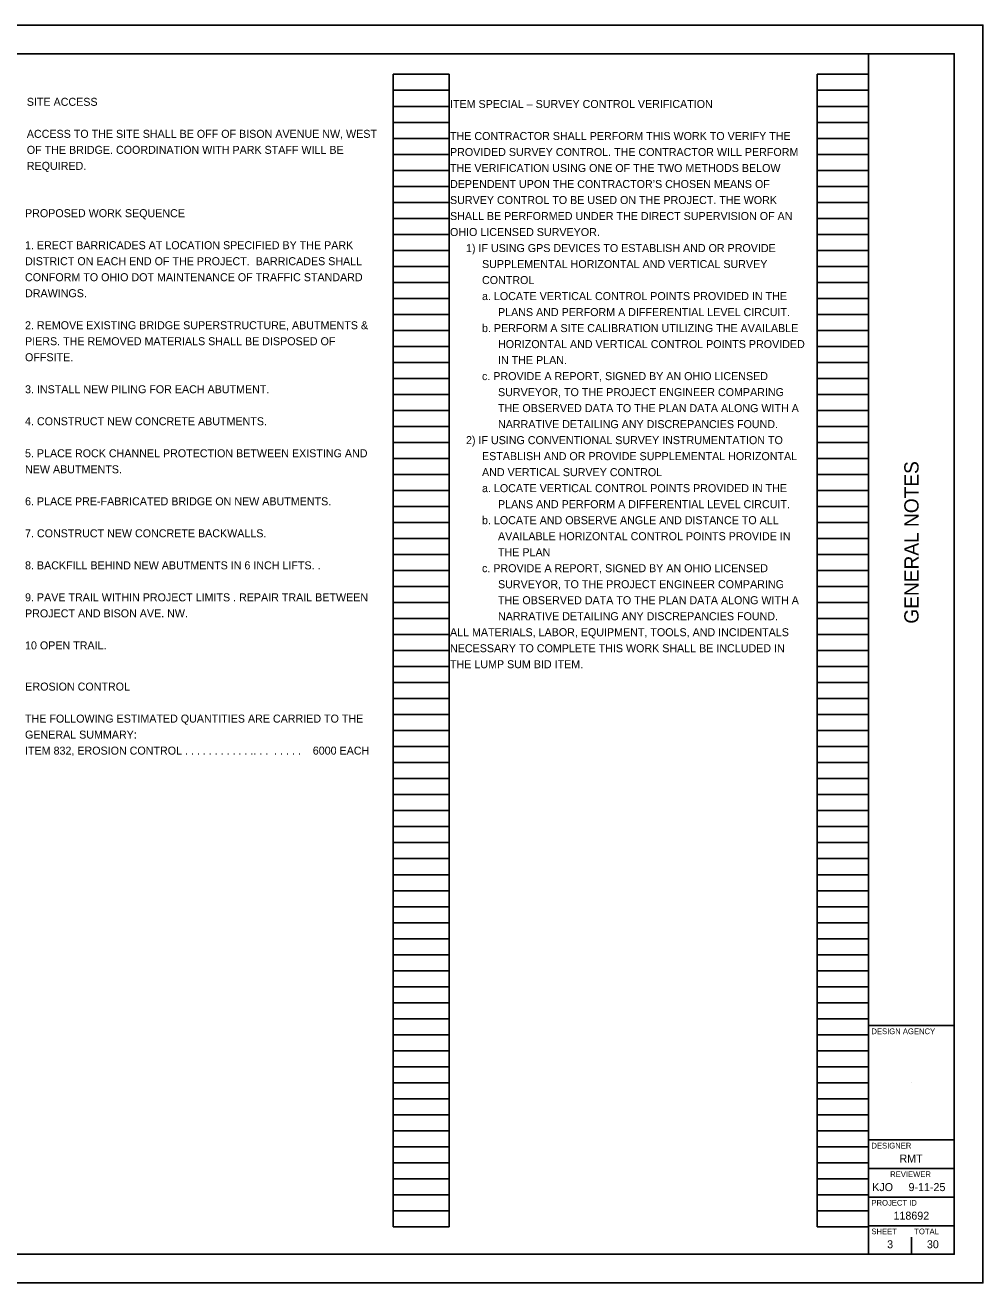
# Model space of a CAD drawing. Extents: x 4.7 to 38.7, y 13.7 to 35.7.
# Drawn here: x 21.95 to 38.7, y 13.71 to 35.71 of the extents above; entities that cross this region are included whole.
import ezdxf

# ---------------------------------------------------------------- set-up
doc = ezdxf.new("R2010")
doc.units = 0
for name, color, linetype in [('SH_Border', 7, 'Continuous'), ('SH_Cut_Line', 7, 'Continuous'), ('SH_Data', 7, 'Continuous'), ('SH_Text', 7, 'Continuous')]:
    doc.layers.add(name, color=color, linetype=linetype)

msp = doc.modelspace()

# ---------------------------------------------------------------- linework, layer by layer
at = {"layer": 'SH_Border'}
for p, q in [((36.705, 14.212), (36.705, 35.212)), ((36.705, 18.212), (38.205, 18.212)), ((36.705, 16.212), (38.205, 16.212)), ((36.705, 15.712), (38.205, 15.712)), ((36.705, 15.212), (38.205, 15.212)), ((36.705, 14.712), (38.205, 14.712))]:
    msp.add_line(p, q, dxfattribs=at)
msp.add_lwpolyline([(6.205, 35.212), (38.205, 35.212), (38.205, 14.212), (6.205, 14.212)], close=True, dxfattribs=at)
at = {"layer": 'SH_Cut_Line'}
msp.add_lwpolyline([(4.705, 13.712), (38.705, 13.712), (38.705, 35.712), (4.705, 35.712)], close=True, dxfattribs=at)
at = {"layer": 'SH_Data'}
for p, q in [((28.385, 14.692), (28.385, 34.852)), ((28.385, 34.852), (29.365, 34.852)), ((29.365, 14.692), (29.365, 34.852)), ((35.805, 14.692), (35.805, 34.852)), ((35.805, 34.852), (36.705, 34.852)), ((36.705, 14.692), (36.705, 34.852)), ((28.385, 34.572), (29.365, 34.572)), ((35.805, 34.572), (36.705, 34.572)), ((28.385, 34.292), (29.365, 34.292)), ((35.805, 34.292), (36.705, 34.292)), ((28.385, 34.012), (29.365, 34.012)), ((35.805, 34.012), (36.705, 34.012)), ((28.385, 33.732), (29.365, 33.732)), ((35.805, 33.732), (36.705, 33.732)), ((28.385, 33.452), (29.365, 33.452)), ((35.805, 33.452), (36.705, 33.452)), ((28.385, 33.172), (29.365, 33.172)), ((35.805, 33.172), (36.705, 33.172)), ((28.385, 32.892), (29.365, 32.892)), ((35.805, 32.892), (36.705, 32.892)), ((28.385, 32.612), (29.365, 32.612)), ((35.805, 32.612), (36.705, 32.612)), ((28.385, 32.332), (29.365, 32.332)), ((35.805, 32.332), (36.705, 32.332)), ((28.385, 32.052), (29.365, 32.052)), ((35.805, 32.052), (36.705, 32.052)), ((28.385, 31.772), (29.365, 31.772)), ((35.805, 31.772), (36.705, 31.772)), ((28.385, 31.492), (29.365, 31.492)), ((35.805, 31.492), (36.705, 31.492)), ((28.385, 31.212), (29.365, 31.212)), ((35.805, 31.212), (36.705, 31.212)), ((28.385, 30.932), (29.365, 30.932)), ((35.805, 30.932), (36.705, 30.932)), ((28.385, 30.652), (29.365, 30.652)), ((35.805, 30.652), (36.705, 30.652)), ((28.385, 30.372), (29.365, 30.372)), ((35.805, 30.372), (36.705, 30.372)), ((28.385, 30.092), (29.365, 30.092)), ((35.805, 30.092), (36.705, 30.092)), ((28.385, 29.812), (29.365, 29.812)), ((35.805, 29.812), (36.705, 29.812)), ((28.385, 29.532), (29.365, 29.532)), ((35.805, 29.532), (36.705, 29.532)), ((28.385, 29.252), (29.365, 29.252)), ((35.805, 29.252), (36.705, 29.252)), ((28.385, 28.972), (29.365, 28.972)), ((35.805, 28.972), (36.705, 28.972)), ((28.385, 28.692), (29.365, 28.692)), ((35.805, 28.692), (36.705, 28.692)), ((28.385, 28.412), (29.365, 28.412)), ((35.805, 28.412), (36.705, 28.412)), ((28.385, 28.132), (29.365, 28.132)), ((35.805, 28.132), (36.705, 28.132)), ((28.385, 27.852), (29.365, 27.852)), ((35.805, 27.852), (36.705, 27.852)), ((28.385, 27.572), (29.365, 27.572)), ((35.805, 27.572), (36.705, 27.572)), ((28.385, 27.292), (29.365, 27.292)), ((35.805, 27.292), (36.705, 27.292)), ((28.385, 27.012), (29.365, 27.012)), ((35.805, 27.012), (36.705, 27.012)), ((28.385, 26.732), (29.365, 26.732)), ((35.805, 26.732), (36.705, 26.732)), ((28.385, 26.452), (29.365, 26.452)), ((35.805, 26.452), (36.705, 26.452)), ((28.385, 26.172), (29.365, 26.172)), ((35.805, 26.172), (36.705, 26.172)), ((28.385, 25.892), (29.365, 25.892)), ((35.805, 25.892), (36.705, 25.892)), ((28.385, 25.612), (29.365, 25.612)), ((35.805, 25.612), (36.705, 25.612)), ((28.385, 25.332), (29.365, 25.332)), ((35.805, 25.332), (36.705, 25.332)), ((28.385, 25.052), (29.365, 25.052)), ((35.805, 25.052), (36.705, 25.052)), ((28.385, 24.772), (29.365, 24.772)), ((35.805, 24.772), (36.705, 24.772)), ((28.385, 24.492), (29.365, 24.492)), ((35.805, 24.492), (36.705, 24.492)), ((28.385, 24.212), (29.365, 24.212)), ((35.805, 24.212), (36.705, 24.212)), ((28.385, 23.932), (29.365, 23.932)), ((35.805, 23.932), (36.705, 23.932)), ((28.385, 23.652), (29.365, 23.652)), ((35.805, 23.652), (36.705, 23.652)), ((28.385, 23.372), (29.365, 23.372)), ((35.805, 23.372), (36.705, 23.372)), ((28.385, 23.092), (29.365, 23.092)), ((35.805, 23.092), (36.705, 23.092)), ((28.385, 22.812), (29.365, 22.812)), ((35.805, 22.812), (36.705, 22.812)), ((28.385, 22.532), (29.365, 22.532)), ((35.805, 22.532), (36.705, 22.532)), ((28.385, 22.252), (29.365, 22.252)), ((35.805, 22.252), (36.705, 22.252)), ((28.385, 21.972), (29.365, 21.972)), ((35.805, 21.972), (36.705, 21.972)), ((28.385, 21.692), (29.365, 21.692)), ((35.805, 21.692), (36.705, 21.692)), ((28.385, 21.412), (29.365, 21.412)), ((35.805, 21.412), (36.705, 21.412)), ((28.385, 21.132), (29.365, 21.132)), ((35.805, 21.132), (36.705, 21.132)), ((28.385, 20.852), (29.365, 20.852)), ((35.805, 20.852), (36.705, 20.852)), ((28.385, 20.572), (29.365, 20.572)), ((35.805, 20.572), (36.705, 20.572)), ((28.385, 20.292), (29.365, 20.292)), ((35.805, 20.292), (36.705, 20.292)), ((28.385, 20.012), (29.365, 20.012)), ((35.805, 20.012), (36.705, 20.012)), ((28.385, 19.732), (29.365, 19.732)), ((35.805, 19.732), (36.705, 19.732)), ((28.385, 19.452), (29.365, 19.452)), ((35.805, 19.452), (36.705, 19.452)), ((28.385, 19.172), (29.365, 19.172)), ((35.805, 19.172), (36.705, 19.172)), ((28.385, 18.892), (29.365, 18.892)), ((35.805, 18.892), (36.705, 18.892)), ((28.385, 18.612), (29.365, 18.612)), ((35.805, 18.612), (36.705, 18.612)), ((28.385, 18.332), (29.365, 18.332)), ((35.805, 18.332), (36.705, 18.332)), ((28.385, 18.052), (29.365, 18.052)), ((35.805, 18.052), (36.705, 18.052)), ((28.385, 17.772), (29.365, 17.772)), ((35.805, 17.772), (36.705, 17.772)), ((28.385, 17.492), (29.365, 17.492)), ((35.805, 17.492), (36.705, 17.492)), ((28.385, 17.212), (29.365, 17.212)), ((35.805, 17.212), (36.705, 17.212)), ((37.455, 17.212), (37.455, 17.212)), ((28.385, 16.932), (29.365, 16.932)), ((35.805, 16.932), (36.705, 16.932)), ((28.385, 16.652), (29.365, 16.652)), ((35.805, 16.652), (36.705, 16.652)), ((28.385, 16.372), (29.365, 16.372)), ((35.805, 16.372), (36.705, 16.372)), ((28.385, 16.092), (29.365, 16.092)), ((35.805, 16.092), (36.705, 16.092)), ((28.385, 15.812), (29.365, 15.812)), ((35.805, 15.812), (36.705, 15.812)), ((28.385, 15.532), (29.365, 15.532)), ((35.805, 15.532), (36.705, 15.532)), ((28.385, 15.252), (29.365, 15.252)), ((35.805, 15.252), (36.705, 15.252)), ((28.385, 14.972), (29.365, 14.972)), ((35.805, 14.972), (36.705, 14.972)), ((28.385, 14.692), (29.365, 14.692)), ((35.805, 14.692), (36.705, 14.692)), ((37.08, 14.387), (37.08, 14.387)), ((37.455, 14.212), (37.455, 14.512))]:
    msp.add_line(p, q, dxfattribs=at)

# ---------------------------------------------------------------- texts
msp.add_text('GENERAL NOTES', height=0.25, rotation=90, dxfattribs=at).set_placement((37.58, 25.243))
for s, height, p in [('DESIGN AGENCY', 0.1, (36.755, 18.062)), ('DESIGNER', 0.1, (36.755, 16.062)), ('RMT', 0.14, (37.245, 15.817)), ('REVIEWER', 0.1, (37.083, 15.562)), ('KJO', 0.14, (36.769, 15.317)), ('9-11-25', 0.14, (37.404, 15.317)), ('PROJECT ID', 0.1, (36.755, 15.062)), ('118692', 0.14, (37.141, 14.817)), ('SHEET', 0.1, (36.755, 14.562)), ('TOTAL', 0.1, (37.505, 14.562)), ('3', 0.14, (37.03, 14.317)), ('30', 0.14, (37.726, 14.317))]:
    msp.add_text(s, height=height, dxfattribs=at).set_placement(p)
at = {"layer": 'SH_Text'}
for s, p in [('SITE ACCESS', (21.976, 34.301)), ('ITEM SPECIAL – SURVEY CONTROL VERIFICATION', (29.381, 34.263)), ('ACCESS TO THE SITE SHALL BE OFF OF BISON AVENUE NW, WEST ', (21.976, 33.741)), ('THE CONTRACTOR SHALL PERFORM THIS WORK TO VERIFY THE ', (29.381, 33.703)), ('OF THE BRIDGE. COORDINATION WITH PARK STAFF WILL BE ', (21.976, 33.461)), ('PROVIDED SURVEY CONTROL. THE CONTRACTOR WILL PERFORM ', (29.381, 33.423)), ('REQUIRED.', (21.976, 33.181)), ('THE VERIFICATION USING ONE OF THE TWO METHODS BELOW ', (29.381, 33.143)), ('DEPENDENT UPON THE CONTRACTOR’S CHOSEN MEANS OF', (29.381, 32.863)), ('SURVEY CONTROL TO BE USED ON THE PROJECT. THE WORK ', (29.381, 32.583)), ('PROPOSED WORK SEQUENCE', (21.945, 32.353)), ('SHALL BE PERFORMED UNDER THE DIRECT SUPERVISION OF AN ', (29.381, 32.303)), ('OHIO LICENSED SURVEYOR.', (29.381, 32.023)), ('1. ERECT BARRICADES AT LOCATION SPECIFIED BY THE PARK ', (21.945, 31.793)), ('1) IF USING GPS DEVICES TO ESTABLISH AND OR PROVIDE ', (29.661, 31.743)), ('DISTRICT ON EACH END OF THE PROJECT.  BARRICADES SHALL ', (21.945, 31.513)), ('SUPPLEMENTAL HORIZONTAL AND VERTICAL SURVEY ', (29.941, 31.463)), ('CONFORM TO OHIO DOT MAINTENANCE OF TRAFFIC STANDARD ', (21.945, 31.233)), ('CONTROL', (29.941, 31.183)), ('DRAWINGS. ', (21.945, 30.953)), ('a. LOCATE VERTICAL CONTROL POINTS PROVIDED IN THE ', (29.941, 30.903)), ('PLANS AND PERFORM A DIFFERENTIAL LEVEL CIRCUIT.', (30.221, 30.623)), ('2. REMOVE EXISTING BRIDGE SUPERSTRUCTURE, ABUTMENTS & ', (21.945, 30.393)), ('b. PERFORM A SITE CALIBRATION UTILIZING THE AVAILABLE ', (29.941, 30.343)), ('PIERS. THE REMOVED MATERIALS SHALL BE DISPOSED OF ', (21.945, 30.113)), ('HORIZONTAL AND VERTICAL CONTROL POINTS PROVIDED ', (30.221, 30.063)), ('OFFSITE.', (21.945, 29.833)), ('IN THE PLAN.', (30.221, 29.783)), ('c. PROVIDE A REPORT, SIGNED BY AN OHIO LICENSED ', (29.941, 29.503)), ('3. INSTALL NEW PILING FOR EACH ABUTMENT.', (21.945, 29.273)), ('SURVEYOR, TO THE PROJECT ENGINEER COMPARING ', (30.221, 29.223)), ('THE OBSERVED DATA TO THE PLAN DATA ALONG WITH A ', (30.221, 28.943)), ('4. CONSTRUCT NEW CONCRETE ABUTMENTS.', (21.945, 28.713)), ('NARRATIVE DETAILING ANY DISCREPANCIES FOUND.', (30.221, 28.663)), ('2) IF USING CONVENTIONAL SURVEY INSTRUMENTATION TO ', (29.661, 28.383)), ('5. PLACE ROCK CHANNEL PROTECTION BETWEEN EXISTING AND ', (21.945, 28.153)), ('ESTABLISH AND OR PROVIDE SUPPLEMENTAL HORIZONTAL ', (29.941, 28.103)), ('NEW ABUTMENTS.', (21.945, 27.873)), ('AND VERTICAL SURVEY CONTROL', (29.941, 27.823)), ('a. LOCATE VERTICAL CONTROL POINTS PROVIDED IN THE ', (29.941, 27.543)), ('6. PLACE PRE-FABRICATED BRIDGE ON NEW ABUTMENTS.', (21.945, 27.313)), ('PLANS AND PERFORM A DIFFERENTIAL LEVEL CIRCUIT.', (30.221, 27.263)), ('b. LOCATE AND OBSERVE ANGLE AND DISTANCE TO ALL ', (29.941, 26.983)), ('7. CONSTRUCT NEW CONCRETE BACKWALLS.', (21.945, 26.753)), ('AVAILABLE HORIZONTAL CONTROL POINTS PROVIDE IN ', (30.221, 26.703)), ('THE PLAN', (30.221, 26.423)), ('8. BACKFILL BEHIND NEW ABUTMENTS IN 6 INCH LIFTS. .', (21.945, 26.193)), ('c. PROVIDE A REPORT, SIGNED BY AN OHIO LICENSED ', (29.941, 26.143)), ('SURVEYOR, TO THE PROJECT ENGINEER COMPARING ', (30.221, 25.863)), ('9. PAVE TRAIL WITHIN PROJECT LIMITS . REPAIR TRAIL BETWEEN ', (21.945, 25.633)), ('THE OBSERVED DATA TO THE PLAN DATA ALONG WITH A ', (30.221, 25.583)), ('PROJECT AND BISON AVE. NW. ', (21.945, 25.353)), ('NARRATIVE DETAILING ANY DISCREPANCIES FOUND. ', (30.221, 25.303)), ('ALL MATERIALS, LABOR, EQUIPMENT, TOOLS, AND INCIDENTALS ', (29.381, 25.023)), ('10 OPEN TRAIL.', (21.945, 24.793)), ('NECESSARY TO COMPLETE THIS WORK SHALL BE INCLUDED IN ', (29.381, 24.743)), ('THE LUMP SUM BID ITEM.', (29.381, 24.463)), ('E', (21.945, 24.072)), ('ROSION CONTROL', (22.075, 24.072)), ('THE FOLLOWING ESTIMATED QUANTITIES ARE CARRIED TO THE ', (21.945, 23.512)), ('GENERAL SUMMARY:  ', (21.945, 23.232)), ('ITEM 832, EROSION CONTROL . . . . . . . . . . . .. . .  . . . . .    6000 EACH', (21.945, 22.952))]:
    msp.add_text(s, height=0.14, dxfattribs=at).set_placement(p)

doc.saveas('drawing.dxf')
